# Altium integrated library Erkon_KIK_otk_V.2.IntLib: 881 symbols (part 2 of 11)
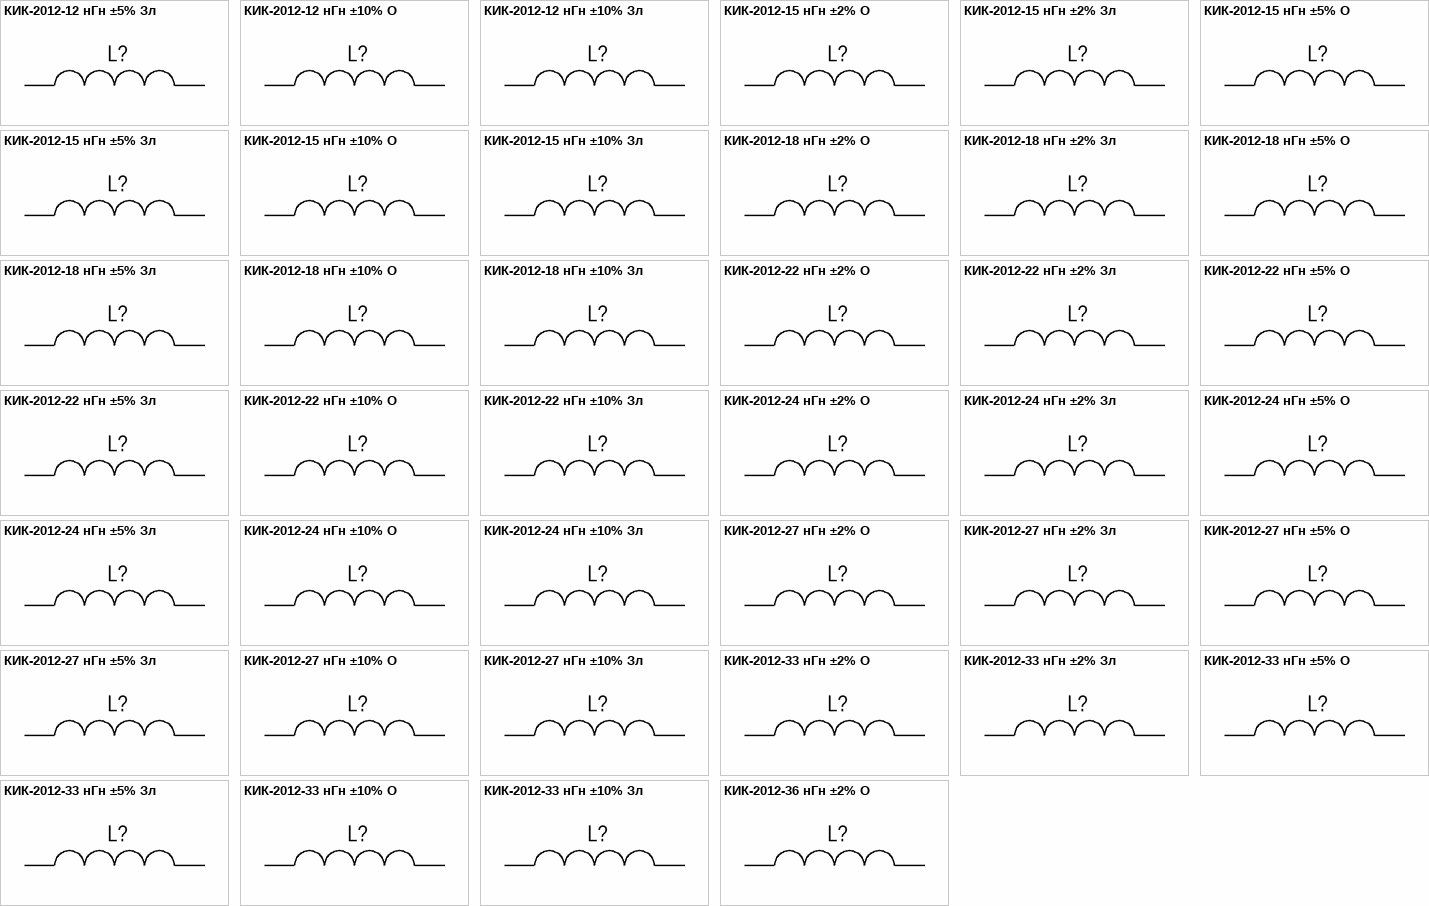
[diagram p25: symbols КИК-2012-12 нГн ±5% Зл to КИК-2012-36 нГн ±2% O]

## КИК-2012-36 нГн ±2% O
designator L?, comment 36 нГн ±2%  (value not drawn)
Катушка индуктивности с керамическим сердечником и  финишным покрытием контактных площадок оловом; Номиналиная индуктивность: 36 нГн; Добротность, не менее: 50; Резонансная частота, не менее: 1.90 ГГц; Сопротивление обмотки постоянноми току, не более: 0.27 Ом; Допустимый ток обмотки: 500 мА; Диапазон рабочих температур: от -60 до +125 ℃; Упаковка: Катушка и лента; Типоразмер: 2012 (0805); Технология монтажа: SMT; Изготовитель: АО "НПО "ЭРКОН"
footprint КИК-2012-O (Катушка индуктивности с керамическим сердечником типоразмер 2012(0805))
pins: 1, 2

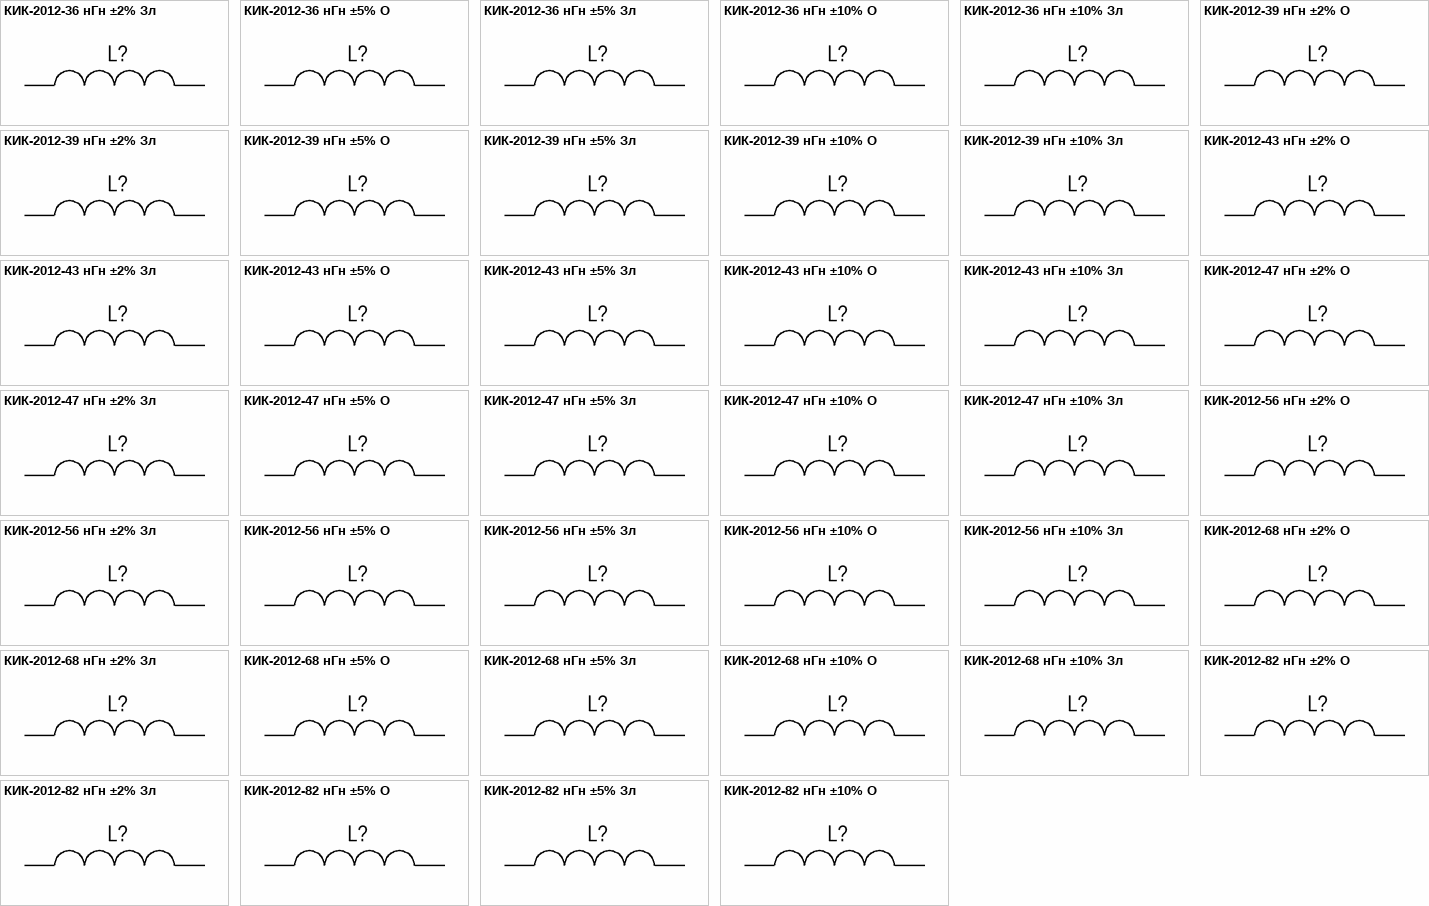
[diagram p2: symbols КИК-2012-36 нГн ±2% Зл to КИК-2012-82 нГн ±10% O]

## КИК-2012-36 нГн ±2% Зл
designator L?, comment 36 нГн ±2%  (value not drawn)
Катушка индуктивности с керамическим сердечником и золотым покрытием контактных площадок; Номиналиная индуктивность: 36 нГн; Добротность, не менее: 50; Резонансная частота, не менее: 1.90 ГГц; Сопротивление обмотки постоянноми току, не более: 0.27 Ом; Допустимый ток обмотки: 500 мА; Диапазон рабочих температур: от -60 до +125 ℃; Упаковка: Катушка и лента; Типоразмер: 2012 (0805); Технология монтажа: SMT; Изготовитель: АО "НПО "ЭРКОН"
footprint КИК-2012-Зл (Катушка индуктивности с керамическим сердечникомтипоразмер 2012(0805))
pins: 1, 2

## КИК-2012-36 нГн ±5% O
designator L?, comment 36 нГн ±5%  (value not drawn)
Катушка индуктивности с керамическим сердечником и  финишным покрытием контактных площадок оловом; Номиналиная индуктивность: 36 нГн; Добротность, не менее: 50; Резонансная частота, не менее: 1.90 ГГц; Сопротивление обмотки постоянноми току, не более: 0.27 Ом; Допустимый ток обмотки: 500 мА; Диапазон рабочих температур: от -60 до +125 ℃; Упаковка: Катушка и лента; Типоразмер: 2012 (0805); Технология монтажа: SMT; Изготовитель: АО "НПО "ЭРКОН"
footprint КИК-2012-O (Катушка индуктивности с керамическим сердечником типоразмер 2012(0805))
pins: 1, 2

## КИК-2012-36 нГн ±5% Зл
designator L?, comment 36 нГн ±5%  (value not drawn)
Катушка индуктивности с керамическим сердечником и золотым покрытием контактных площадок; Номиналиная индуктивность: 36 нГн; Добротность, не менее: 50; Резонансная частота, не менее: 1.90 ГГц; Сопротивление обмотки постоянноми току, не более: 0.27 Ом; Допустимый ток обмотки: 500 мА; Диапазон рабочих температур: от -60 до +125 ℃; Упаковка: Катушка и лента; Типоразмер: 2012 (0805); Технология монтажа: SMT; Изготовитель: АО "НПО "ЭРКОН"
footprint КИК-2012-Зл (Катушка индуктивности с керамическим сердечникомтипоразмер 2012(0805))
pins: 1, 2

## КИК-2012-36 нГн ±10% O
designator L?, comment 36 нГн ±10%  (value not drawn)
Катушка индуктивности с керамическим сердечником и  финишным покрытием контактных площадок оловом; Номиналиная индуктивность: 36 нГн; Добротность, не менее: 50; Резонансная частота, не менее: 1.90 ГГц; Сопротивление обмотки постоянноми току, не более: 0.27 Ом; Допустимый ток обмотки: 500 мА; Диапазон рабочих температур: от -60 до +125 ℃; Упаковка: Катушка и лента; Типоразмер: 2012 (0805); Технология монтажа: SMT; Изготовитель: АО "НПО "ЭРКОН"
footprint КИК-2012-O (Катушка индуктивности с керамическим сердечником типоразмер 2012(0805))
pins: 1, 2

## КИК-2012-36 нГн ±10% Зл
designator L?, comment 36 нГн ±10%  (value not drawn)
Катушка индуктивности с керамическим сердечником и золотым покрытием контактных площадок; Номиналиная индуктивность: 36 нГн; Добротность, не менее: 50; Резонансная частота, не менее: 1.90 ГГц; Сопротивление обмотки постоянноми току, не более: 0.27 Ом; Допустимый ток обмотки: 500 мА; Диапазон рабочих температур: от -60 до +125 ℃; Упаковка: Катушка и лента; Типоразмер: 2012 (0805); Технология монтажа: SMT; Изготовитель: АО "НПО "ЭРКОН"
footprint КИК-2012-Зл (Катушка индуктивности с керамическим сердечникомтипоразмер 2012(0805))
pins: 1, 2

## КИК-2012-39 нГн ±2% O
designator L?, comment 39 нГн ±2%  (value not drawn)
Катушка индуктивности с керамическим сердечником и  финишным покрытием контактных площадок оловом; Номиналиная индуктивность: 39 нГн; Добротность, не менее: 60; Резонансная частота, не менее: 2.0 ГГц; Сопротивление обмотки постоянноми току, не более: 0.29 Ом; Допустимый ток обмотки: 500 мА; Диапазон рабочих температур: от -60 до +125 ℃; Упаковка: Катушка и лента; Типоразмер: 2012 (0805); Технология монтажа: SMT; Изготовитель: АО "НПО "ЭРКОН"
footprint КИК-2012-O (Катушка индуктивности с керамическим сердечником типоразмер 2012(0805))
pins: 1, 2

## КИК-2012-39 нГн ±2% Зл
designator L?, comment 39 нГн ±2%  (value not drawn)
Катушка индуктивности с керамическим сердечником и золотым покрытием контактных площадок; Номиналиная индуктивность: 39 нГн; Добротность, не менее: 60; Резонансная частота, не менее: 2.0 ГГц; Сопротивление обмотки постоянноми току, не более: 0.29 Ом; Допустимый ток обмотки: 500 мА; Диапазон рабочих температур: от -60 до +125 ℃; Упаковка: Катушка и лента; Типоразмер: 2012 (0805); Технология монтажа: SMT; Изготовитель: АО "НПО "ЭРКОН"
footprint КИК-2012-Зл (Катушка индуктивности с керамическим сердечникомтипоразмер 2012(0805))
pins: 1, 2

## КИК-2012-39 нГн ±5% O
designator L?, comment 39 нГн ±5%  (value not drawn)
Катушка индуктивности с керамическим сердечником и  финишным покрытием контактных площадок оловом; Номиналиная индуктивность: 39 нГн; Добротность, не менее: 60; Резонансная частота, не менее: 2.0 ГГц; Сопротивление обмотки постоянноми току, не более: 0.29 Ом; Допустимый ток обмотки: 500 мА; Диапазон рабочих температур: от -60 до +125 ℃; Упаковка: Катушка и лента; Типоразмер: 2012 (0805); Технология монтажа: SMT; Изготовитель: АО "НПО "ЭРКОН"
footprint КИК-2012-O (Катушка индуктивности с керамическим сердечником типоразмер 2012(0805))
pins: 1, 2

## КИК-2012-39 нГн ±5% Зл
designator L?, comment 39 нГн ±5%  (value not drawn)
Катушка индуктивности с керамическим сердечником и золотым покрытием контактных площадок; Номиналиная индуктивность: 39 нГн; Добротность, не менее: 60; Резонансная частота, не менее: 2.0 ГГц; Сопротивление обмотки постоянноми току, не более: 0.29 Ом; Допустимый ток обмотки: 500 мА; Диапазон рабочих температур: от -60 до +125 ℃; Упаковка: Катушка и лента; Типоразмер: 2012 (0805); Технология монтажа: SMT; Изготовитель: АО "НПО "ЭРКОН"
footprint КИК-2012-Зл (Катушка индуктивности с керамическим сердечникомтипоразмер 2012(0805))
pins: 1, 2

## КИК-2012-39 нГн ±10% O
designator L?, comment 39 нГн ±10%  (value not drawn)
Катушка индуктивности с керамическим сердечником и  финишным покрытием контактных площадок оловом; Номиналиная индуктивность: 39 нГн; Добротность, не менее: 60; Резонансная частота, не менее: 2.0 ГГц; Сопротивление обмотки постоянноми току, не более: 0.29 Ом; Допустимый ток обмотки: 500 мА; Диапазон рабочих температур: от -60 до +125 ℃; Упаковка: Катушка и лента; Типоразмер: 2012 (0805); Технология монтажа: SMT; Изготовитель: АО "НПО "ЭРКОН"
footprint КИК-2012-O (Катушка индуктивности с керамическим сердечником типоразмер 2012(0805))
pins: 1, 2

## КИК-2012-39 нГн ±10% Зл
designator L?, comment 39 нГн ±10%  (value not drawn)
Катушка индуктивности с керамическим сердечником и золотым покрытием контактных площадок; Номиналиная индуктивность: 39 нГн; Добротность, не менее: 60; Резонансная частота, не менее: 2.0 ГГц; Сопротивление обмотки постоянноми току, не более: 0.29 Ом; Допустимый ток обмотки: 500 мА; Диапазон рабочих температур: от -60 до +125 ℃; Упаковка: Катушка и лента; Типоразмер: 2012 (0805); Технология монтажа: SMT; Изготовитель: АО "НПО "ЭРКОН"
footprint КИК-2012-Зл (Катушка индуктивности с керамическим сердечникомтипоразмер 2012(0805))
pins: 1, 2

## КИК-2012-43 нГн ±2% O
designator L?, comment 43 нГн ±2%  (value not drawn)
Катушка индуктивности с керамическим сердечником и  финишным покрытием контактных площадок оловом; Номиналиная индуктивность: 43 нГн; Добротность, не менее: 60; Резонансная частота, не менее: 1.8 ГГц; Сопротивление обмотки постоянноми току, не более: 0.34 Ом; Допустимый ток обмотки: 500 мА; Диапазон рабочих температур: от -60 до +125 ℃; Упаковка: Катушка и лента; Типоразмер: 2012 (0805); Технология монтажа: SMT; Изготовитель: АО "НПО "ЭРКОН"
footprint КИК-2012-O (Катушка индуктивности с керамическим сердечником типоразмер 2012(0805))
pins: 1, 2

## КИК-2012-43 нГн ±2% Зл
designator L?, comment 43 нГн ±2%  (value not drawn)
Катушка индуктивности с керамическим сердечником и золотым покрытием контактных площадок; Номиналиная индуктивность: 43 нГн; Добротность, не менее: 60; Резонансная частота, не менее: 1.8 ГГц; Сопротивление обмотки постоянноми току, не более: 0.34 Ом; Допустимый ток обмотки: 500 мА; Диапазон рабочих температур: от -60 до +125 ℃; Упаковка: Катушка и лента; Типоразмер: 2012 (0805); Технология монтажа: SMT; Изготовитель: АО "НПО "ЭРКОН"
footprint КИК-2012-Зл (Катушка индуктивности с керамическим сердечникомтипоразмер 2012(0805))
pins: 1, 2

## КИК-2012-43 нГн ±5% O
designator L?, comment 43 нГн ±5%  (value not drawn)
Катушка индуктивности с керамическим сердечником и  финишным покрытием контактных площадок оловом; Номиналиная индуктивность: 43 нГн; Добротность, не менее: 60; Резонансная частота, не менее: 1.8 ГГц; Сопротивление обмотки постоянноми току, не более: 0.34 Ом; Допустимый ток обмотки: 500 мА; Диапазон рабочих температур: от -60 до +125 ℃; Упаковка: Катушка и лента; Типоразмер: 2012 (0805); Технология монтажа: SMT; Изготовитель: АО "НПО "ЭРКОН"
footprint КИК-2012-O (Катушка индуктивности с керамическим сердечником типоразмер 2012(0805))
pins: 1, 2

## КИК-2012-43 нГн ±5% Зл
designator L?, comment 43 нГн ±5%  (value not drawn)
Катушка индуктивности с керамическим сердечником и золотым покрытием контактных площадок; Номиналиная индуктивность: 43 нГн; Добротность, не менее: 60; Резонансная частота, не менее: 1.8 ГГц; Сопротивление обмотки постоянноми току, не более: 0.34 Ом; Допустимый ток обмотки: 500 мА; Диапазон рабочих температур: от -60 до +125 ℃; Упаковка: Катушка и лента; Типоразмер: 2012 (0805); Технология монтажа: SMT; Изготовитель: АО "НПО "ЭРКОН"
footprint КИК-2012-Зл (Катушка индуктивности с керамическим сердечникомтипоразмер 2012(0805))
pins: 1, 2

## КИК-2012-43 нГн ±10% O
designator L?, comment 43 нГн ±10%  (value not drawn)
Катушка индуктивности с керамическим сердечником и  финишным покрытием контактных площадок оловом; Номиналиная индуктивность: 43 нГн; Добротность, не менее: 60; Резонансная частота, не менее: 1.8 ГГц; Сопротивление обмотки постоянноми току, не более: 0.34 Ом; Допустимый ток обмотки: 500 мА; Диапазон рабочих температур: от -60 до +125 ℃; Упаковка: Катушка и лента; Типоразмер: 2012 (0805); Технология монтажа: SMT; Изготовитель: АО "НПО "ЭРКОН"
footprint КИК-2012-O (Катушка индуктивности с керамическим сердечником типоразмер 2012(0805))
pins: 1, 2

## КИК-2012-43 нГн ±10% Зл
designator L?, comment 43 нГн ±10%  (value not drawn)
Катушка индуктивности с керамическим сердечником и золотым покрытием контактных площадок; Номиналиная индуктивность: 43 нГн; Добротность, не менее: 60; Резонансная частота, не менее: 1.8 ГГц; Сопротивление обмотки постоянноми току, не более: 0.34 Ом; Допустимый ток обмотки: 500 мА; Диапазон рабочих температур: от -60 до +125 ℃; Упаковка: Катушка и лента; Типоразмер: 2012 (0805); Технология монтажа: SMT; Изготовитель: АО "НПО "ЭРКОН"
footprint КИК-2012-Зл (Катушка индуктивности с керамическим сердечникомтипоразмер 2012(0805))
pins: 1, 2

## КИК-2012-47 нГн ±2% O
designator L?, comment 47 нГн ±2%  (value not drawn)
Катушка индуктивности с керамическим сердечником и  финишным покрытием контактных площадок оловом; Номиналиная индуктивность: 47 нГн; Допускаемое отклонение индуктивности: ±5%; Добротность, не менее: 60; Резонансная частота, не менее: 1.7 ГГц; Сопротивление обмотки постоянноми току, не более: 0.31 Ом; Допустимый ток обмотки: 500 мА; Диапазон рабочих температур: от -60 до +125 ℃; Упаковка: Катушка и лента; Типоразмер: 2012 (0805); Технология монтажа: SMT; Изготовитель: АО "НПО "ЭРКОН"
footprint КИК-2012-O (Катушка индуктивности с керамическим сердечником типоразмер 2012(0805))
pins: 1, 2

## КИК-2012-47 нГн ±2% Зл
designator L?, comment 47 нГн ±2%  (value not drawn)
Катушка индуктивности с керамическим сердечником и золотым покрытием контактных площадок; Номиналиная индуктивность: 47 нГн; Добротность, не менее: 60; Резонансная частота, не менее: 1.7 ГГц; Сопротивление обмотки постоянноми току, не более: 0.31 Ом; Допустимый ток обмотки: 500 мА; Диапазон рабочих температур: от -60 до +125 ℃; Упаковка: Катушка и лента; Типоразмер: 2012 (0805); Технология монтажа: SMT; Изготовитель: АО "НПО "ЭРКОН"
footprint КИК-2012-Зл (Катушка индуктивности с керамическим сердечникомтипоразмер 2012(0805))
pins: 1, 2

## КИК-2012-47 нГн ±5% O
designator L?, comment 47 нГн ±5%  (value not drawn)
Катушка индуктивности с керамическим сердечником и  финишным покрытием контактных площадок оловом; Номиналиная индуктивность: 47 нГн; Добротность, не менее: 60; Резонансная частота, не менее: 1.7 ГГц; Сопротивление обмотки постоянноми току, не более: 0.31 Ом; Допустимый ток обмотки: 500 мА; Диапазон рабочих температур: от -60 до +125 ℃; Упаковка: Катушка и лента; Типоразмер: 2012 (0805); Технология монтажа: SMT; Изготовитель: АО "НПО "ЭРКОН"
footprint КИК-2012-O (Катушка индуктивности с керамическим сердечником типоразмер 2012(0805))
pins: 1, 2

## КИК-2012-47 нГн ±5% Зл
designator L?, comment 47 нГн ±5%  (value not drawn)
Катушка индуктивности с керамическим сердечником и золотым покрытием контактных площадок; Номиналиная индуктивность: 47 нГн; Добротность, не менее: 60; Резонансная частота, не менее: 1.7 ГГц; Сопротивление обмотки постоянноми току, не более: 0.31 Ом; Допустимый ток обмотки: 500 мА; Диапазон рабочих температур: от -60 до +125 ℃; Упаковка: Катушка и лента; Типоразмер: 2012 (0805); Технология монтажа: SMT; Изготовитель: АО "НПО "ЭРКОН"
footprint КИК-2012-Зл (Катушка индуктивности с керамическим сердечникомтипоразмер 2012(0805))
pins: 1, 2

## КИК-2012-47 нГн ±10% O
designator L?, comment 47 нГн ±10%  (value not drawn)
Катушка индуктивности с керамическим сердечником и  финишным покрытием контактных площадок оловом; Номиналиная индуктивность: 47 нГн; Добротность, не менее: 60; Резонансная частота, не менее: 1.7 ГГц; Сопротивление обмотки постоянноми току, не более: 0.31 Ом; Допустимый ток обмотки: 500 мА; Диапазон рабочих температур: от -60 до +125 ℃; Упаковка: Катушка и лента; Типоразмер: 2012 (0805); Технология монтажа: SMT; Изготовитель: АО "НПО "ЭРКОН"
footprint КИК-2012-O (Катушка индуктивности с керамическим сердечником типоразмер 2012(0805))
pins: 1, 2

## КИК-2012-47 нГн ±10% Зл
designator L?, comment 47 нГн ±10%  (value not drawn)
Катушка индуктивности с керамическим сердечником и золотым покрытием контактных площадок; Номиналиная индуктивность: 47 нГн; Добротность, не менее: 60; Резонансная частота, не менее: 1.7 ГГц; Сопротивление обмотки постоянноми току, не более: 0.31 Ом; Допустимый ток обмотки: 500 мА; Диапазон рабочих температур: от -60 до +125 ℃; Упаковка: Катушка и лента; Типоразмер: 2012 (0805); Технология монтажа: SMT; Изготовитель: АО "НПО "ЭРКОН"
footprint КИК-2012-Зл (Катушка индуктивности с керамическим сердечникомтипоразмер 2012(0805))
pins: 1, 2

## КИК-2012-56 нГн ±2% O
designator L?, comment 47 нГн ±2%  (value not drawn)
Катушка индуктивности с керамическим сердечником и  финишным покрытием контактных площадок оловом; Номиналиная индуктивность: 56 нГн; Добротность, не менее: 60; Резонансная частота, не менее: 1.6 ГГц; Сопротивление обмотки постоянноми току, не более: 0.34 Ом; Допустимый ток обмотки: 500 мА; Диапазон рабочих температур: от -60 до +125 ℃; Упаковка: Катушка и лента; Типоразмер: 2012 (0805); Технология монтажа: SMT; Изготовитель: АО "НПО "ЭРКОН"
footprint КИК-2012-O (Катушка индуктивности с керамическим сердечником типоразмер 2012(0805))
pins: 1, 2

## КИК-2012-56 нГн ±2% Зл
designator L?, comment 56 нГн ±2%  (value not drawn)
Катушка индуктивности с керамическим сердечником и золотым покрытием контактных площадок; Номиналиная индуктивность: 56 нГн; Добротность, не менее: 60; Резонансная частота, не менее: 1.6 ГГц; Сопротивление обмотки постоянноми току, не более: 0.34 Ом; Допустимый ток обмотки: 500 мА; Диапазон рабочих температур: от -60 до +125 ℃; Упаковка: Катушка и лента; Типоразмер: 2012 (0805); Технология монтажа: SMT; Изготовитель: АО "НПО "ЭРКОН"
footprint КИК-2012-Зл (Катушка индуктивности с керамическим сердечникомтипоразмер 2012(0805))
pins: 1, 2

## КИК-2012-56 нГн ±5% O
designator L?, comment 47 нГн ±5%  (value not drawn)
Катушка индуктивности с керамическим сердечником и  финишным покрытием контактных площадок оловом; Номиналиная индуктивность: 56 нГн; Добротность, не менее: 60; Резонансная частота, не менее: 1.6 ГГц; Сопротивление обмотки постоянноми току, не более: 0.34 Ом; Допустимый ток обмотки: 500 мА; Диапазон рабочих температур: от -60 до +125 ℃; Упаковка: Катушка и лента; Типоразмер: 2012 (0805); Технология монтажа: SMT; Изготовитель: АО "НПО "ЭРКОН"
footprint КИК-2012-O (Катушка индуктивности с керамическим сердечником типоразмер 2012(0805))
pins: 1, 2

## КИК-2012-56 нГн ±5% Зл
designator L?, comment 56 нГн ±5%  (value not drawn)
Катушка индуктивности с керамическим сердечником и золотым покрытием контактных площадок; Номиналиная индуктивность: 56 нГн; Добротность, не менее: 60; Резонансная частота, не менее: 1.6 ГГц; Сопротивление обмотки постоянноми току, не более: 0.34 Ом; Допустимый ток обмотки: 500 мА; Диапазон рабочих температур: от -60 до +125 ℃; Упаковка: Катушка и лента; Типоразмер: 2012 (0805); Технология монтажа: SMT; Изготовитель: АО "НПО "ЭРКОН"
footprint КИК-2012-Зл (Катушка индуктивности с керамическим сердечникомтипоразмер 2012(0805))
pins: 1, 2

## КИК-2012-56 нГн ±10% O
designator L?, comment 56 нГн ±10%  (value not drawn)
Катушка индуктивности с керамическим сердечником и  финишным покрытием контактных площадок оловом; Номиналиная индуктивность: 56 нГн; Добротность, не менее: 60; Резонансная частота, не менее: 1.6 ГГц; Сопротивление обмотки постоянноми току, не более: 0.34 Ом; Допустимый ток обмотки: 500 мА; Диапазон рабочих температур: от -60 до +125 ℃; Упаковка: Катушка и лента; Типоразмер: 2012 (0805); Технология монтажа: SMT; Изготовитель: АО "НПО "ЭРКОН"
footprint КИК-2012-O (Катушка индуктивности с керамическим сердечником типоразмер 2012(0805))
pins: 1, 2

## КИК-2012-56 нГн ±10% Зл
designator L?, comment 56 нГн ±10%  (value not drawn)
Катушка индуктивности с керамическим сердечником и золотым покрытием контактных площадок; Номиналиная индуктивность: 56 нГн; Добротность, не менее: 60; Резонансная частота, не менее: 1.6 ГГц; Сопротивление обмотки постоянноми току, не более: 0.34 Ом; Допустимый ток обмотки: 500 мА; Диапазон рабочих температур: от -60 до +125 ℃; Упаковка: Катушка и лента; Типоразмер: 2012 (0805); Технология монтажа: SMT; Изготовитель: АО "НПО "ЭРКОН"
footprint КИК-2012-Зл (Катушка индуктивности с керамическим сердечникомтипоразмер 2012(0805))
pins: 1, 2

## КИК-2012-68 нГн ±2% O
designator L?, comment 68 нГн ±2%  (value not drawn)
Катушка индуктивности с керамическим сердечником и  финишным покрытием контактных площадок оловом; Номиналиная индуктивность: 68 нГн; Добротность, не менее: 60; Резонансная частота, не менее: 1.5 ГГц; Сопротивление обмотки постоянноми току, не более: 0.38 Ом; Допустимый ток обмотки: 500 мА; Диапазон рабочих температур: от -60 до +125 ℃; Упаковка: Катушка и лента; Типоразмер: 2012 (0805); Технология монтажа: SMT; Изготовитель: АО "НПО "ЭРКОН"
footprint КИК-2012-O (Катушка индуктивности с керамическим сердечником типоразмер 2012(0805))
pins: 1, 2

## КИК-2012-68 нГн ±2% Зл
designator L?, comment 68 нГн ±2%  (value not drawn)
Катушка индуктивности с керамическим сердечником и золотым покрытием контактных площадок; Номиналиная индуктивность: 68 нГн; Добротность, не менее: 60; Резонансная частота, не менее: 1.5 ГГц; Сопротивление обмотки постоянноми току, не более: 0.38 Ом; Допустимый ток обмотки: 500 мА; Диапазон рабочих температур: от -60 до +125 ℃; Упаковка: Катушка и лента; Типоразмер: 2012 (0805); Технология монтажа: SMT; Изготовитель: АО "НПО "ЭРКОН"
footprint КИК-2012-Зл (Катушка индуктивности с керамическим сердечникомтипоразмер 2012(0805))
pins: 1, 2

## КИК-2012-68 нГн ±5% O
designator L?, comment 68 нГн ±5%  (value not drawn)
Катушка индуктивности с керамическим сердечником и  финишным покрытием контактных площадок оловом; Номиналиная индуктивность: 68 нГн; Добротность, не менее: 60; Резонансная частота, не менее: 1.5 ГГц; Сопротивление обмотки постоянноми току, не более: 0.38 Ом; Допустимый ток обмотки: 500 мА; Диапазон рабочих температур: от -60 до +125 ℃; Упаковка: Катушка и лента; Типоразмер: 2012 (0805); Технология монтажа: SMT; Изготовитель: АО "НПО "ЭРКОН"
footprint КИК-2012-O (Катушка индуктивности с керамическим сердечником типоразмер 2012(0805))
pins: 1, 2

## КИК-2012-68 нГн ±5% Зл
designator L?, comment 68 нГн ±5%  (value not drawn)
Катушка индуктивности с керамическим сердечником и золотым покрытием контактных площадок; Номиналиная индуктивность: 68 нГн; Добротность, не менее: 60; Резонансная частота, не менее: 1.5 ГГц; Сопротивление обмотки постоянноми току, не более: 0.38 Ом; Допустимый ток обмотки: 500 мА; Диапазон рабочих температур: от -60 до +125 ℃; Упаковка: Катушка и лента; Типоразмер: 2012 (0805); Технология монтажа: SMT; Изготовитель: АО "НПО "ЭРКОН"
footprint КИК-2012-Зл (Катушка индуктивности с керамическим сердечникомтипоразмер 2012(0805))
pins: 1, 2

## КИК-2012-68 нГн ±10% O
designator L?, comment 68 нГн ±10%  (value not drawn)
Катушка индуктивности с керамическим сердечником и  финишным покрытием контактных площадок оловом; Номиналиная индуктивность: 68 нГн; Добротность, не менее: 60; Резонансная частота, не менее: 1.5 ГГц; Сопротивление обмотки постоянноми току, не более: 0.38 Ом; Допустимый ток обмотки: 500 мА; Диапазон рабочих температур: от -60 до +125 ℃; Упаковка: Катушка и лента; Типоразмер: 2012 (0805); Технология монтажа: SMT; Изготовитель: АО "НПО "ЭРКОН"
footprint КИК-2012-O (Катушка индуктивности с керамическим сердечником типоразмер 2012(0805))
pins: 1, 2

## КИК-2012-68 нГн ±10% Зл
designator L?, comment 68 нГн ±10%  (value not drawn)
Катушка индуктивности с керамическим сердечником и золотым покрытием контактных площадок; Номиналиная индуктивность: 68 нГн; Добротность, не менее: 60; Резонансная частота, не менее: 1.5 ГГц; Сопротивление обмотки постоянноми току, не более: 0.38 Ом; Допустимый ток обмотки: 500 мА; Диапазон рабочих температур: от -60 до +125 ℃; Упаковка: Катушка и лента; Типоразмер: 2012 (0805); Технология монтажа: SMT; Изготовитель: АО "НПО "ЭРКОН"
footprint КИК-2012-Зл (Катушка индуктивности с керамическим сердечникомтипоразмер 2012(0805))
pins: 1, 2

## КИК-2012-82 нГн ±2% O
designator L?, comment 82 нГн ±2%  (value not drawn)
Катушка индуктивности с керамическим сердечником и  финишным покрытием контактных площадок оловом; Номиналиная индуктивность: 82 нГн; Добротность, не менее: 60; Резонансная частота, не менее: 1.33 ГГц; Сопротивление обмотки постоянноми току, не более: 0.42 Ом; Допустимый ток обмотки: 400 мА; Диапазон рабочих температур: от -60 до +125 ℃; Упаковка: Катушка и лента; Типоразмер: 2012 (0805); Технология монтажа: SMT; Изготовитель: АО "НПО "ЭРКОН"
footprint КИК-2012-O (Катушка индуктивности с керамическим сердечником типоразмер 2012(0805))
pins: 1, 2

## КИК-2012-82 нГн ±2% Зл
designator L?, comment 82 нГн ±2%  (value not drawn)
Катушка индуктивности с керамическим сердечником и золотым покрытием контактных площадок; Номиналиная индуктивность: 82 нГн; Добротность, не менее: 60; Резонансная частота, не менее: 1.33 ГГц; Сопротивление обмотки постоянноми току, не более: 0.42 Ом; Допустимый ток обмотки: 400 мА; Диапазон рабочих температур: от -60 до +125 ℃; Упаковка: Катушка и лента; Типоразмер: 2012 (0805); Технология монтажа: SMT; Изготовитель: АО "НПО "ЭРКОН"
footprint КИК-2012-Зл (Катушка индуктивности с керамическим сердечникомтипоразмер 2012(0805))
pins: 1, 2

## КИК-2012-82 нГн ±5% O
designator L?, comment 82 нГн ±5%  (value not drawn)
Катушка индуктивности с керамическим сердечником и  финишным покрытием контактных площадок оловом; Номиналиная индуктивность: 82 нГн; Добротность, не менее: 60; Резонансная частота, не менее: 1.33 ГГц; Сопротивление обмотки постоянноми току, не более: 0.42 Ом; Допустимый ток обмотки: 400 мА; Диапазон рабочих температур: от -60 до +125 ℃; Упаковка: Катушка и лента; Типоразмер: 2012 (0805); Технология монтажа: SMT; Изготовитель: АО "НПО "ЭРКОН"
footprint КИК-2012-O (Катушка индуктивности с керамическим сердечником типоразмер 2012(0805))
pins: 1, 2

## КИК-2012-82 нГн ±5% Зл
designator L?, comment 82 нГн ±5%  (value not drawn)
Катушка индуктивности с керамическим сердечником и золотым покрытием контактных площадок; Номиналиная индуктивность: 82 нГн; Добротность, не менее: 60; Резонансная частота, не менее: 1.33 ГГц; Сопротивление обмотки постоянноми току, не более: 0.42 Ом; Допустимый ток обмотки: 400 мА; Диапазон рабочих температур: от -60 до +125 ℃; Упаковка: Катушка и лента; Типоразмер: 2012 (0805); Технология монтажа: SMT; Изготовитель: АО "НПО "ЭРКОН"
footprint КИК-2012-Зл (Катушка индуктивности с керамическим сердечникомтипоразмер 2012(0805))
pins: 1, 2

## КИК-2012-82 нГн ±10% O
designator L?, comment 82 нГн ±10%  (value not drawn)
Катушка индуктивности с керамическим сердечником и  финишным покрытием контактных площадок оловом; Номиналиная индуктивность: 82 нГн; Добротность, не менее: 60; Резонансная частота, не менее: 1.33 ГГц; Сопротивление обмотки постоянноми току, не более: 0.42 Ом; Допустимый ток обмотки: 400 мА; Диапазон рабочих температур: от -60 до +125 ℃; Упаковка: Катушка и лента; Типоразмер: 2012 (0805); Технология монтажа: SMT; Изготовитель: АО "НПО "ЭРКОН"
footprint КИК-2012-O (Катушка индуктивности с керамическим сердечником типоразмер 2012(0805))
pins: 1, 2

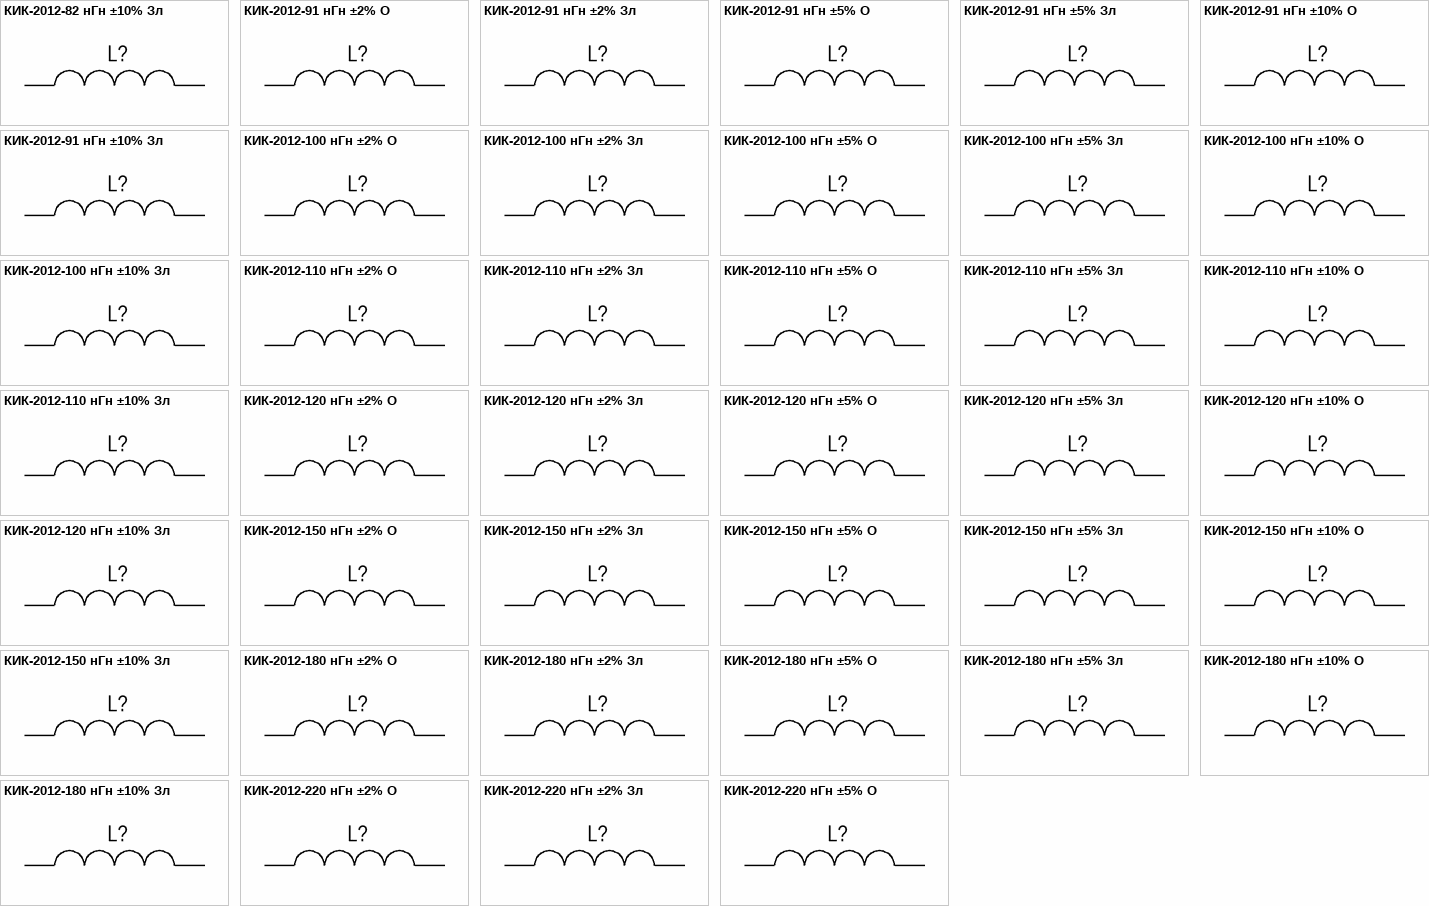
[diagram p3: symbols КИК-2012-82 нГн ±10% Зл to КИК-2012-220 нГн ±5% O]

## КИК-2012-82 нГн ±10% Зл
designator L?, comment 82 нГн ±10%  (value not drawn)
Катушка индуктивности с керамическим сердечником и золотым покрытием контактных площадок; Номиналиная индуктивность: 82 нГн; Добротность, не менее: 60; Резонансная частота, не менее: 1.33 ГГц; Сопротивление обмотки постоянноми току, не более: 0.42 Ом; Допустимый ток обмотки: 400 мА; Диапазон рабочих температур: от -60 до +125 ℃; Упаковка: Катушка и лента; Типоразмер: 2012 (0805); Технология монтажа: SMT; Изготовитель: АО "НПО "ЭРКОН"
footprint КИК-2012-Зл (Катушка индуктивности с керамическим сердечникомтипоразмер 2012(0805))
pins: 1, 2

## КИК-2012-91 нГн ±2% O
designator L?, comment 91 нГн ±2%  (value not drawn)
Катушка индуктивности с керамическим сердечником и  финишным покрытием контактных площадок оловом; Номиналиная индуктивность: 91нГн; Добротность, не менее: 60; Резонансная частота, не менее: 1.33 ГГц; Сопротивление обмотки постоянноми току, не более: 0.48 Ом; Допустимый ток обмотки: 400 мА; Диапазон рабочих температур: от -60 до +125 ℃; Упаковка: Катушка и лента; Типоразмер: 2012 (0805); Технология монтажа: SMT; Изготовитель: АО "НПО "ЭРКОН"
footprint КИК-2012-O (Катушка индуктивности с керамическим сердечником типоразмер 2012(0805))
pins: 1, 2

## КИК-2012-91 нГн ±2% Зл
designator L?, comment 91 нГн ±2%  (value not drawn)
Катушка индуктивности с керамическим сердечником и золотым покрытием контактных площадок; Номиналиная индуктивность: 91нГн; Добротность, не менее: 60; Резонансная частота, не менее: 1.33 ГГц; Сопротивление обмотки постоянноми току, не более: 0.48 Ом; Допустимый ток обмотки: 400 мА; Диапазон рабочих температур: от -60 до +125 ℃; Упаковка: Катушка и лента; Типоразмер: 2012 (0805); Технология монтажа: SMT; Изготовитель: АО "НПО "ЭРКОН"
footprint КИК-2012-Зл (Катушка индуктивности с керамическим сердечникомтипоразмер 2012(0805))
pins: 1, 2

## КИК-2012-91 нГн ±5% O
designator L?, comment 91 нГн ±5%  (value not drawn)
Катушка индуктивности с керамическим сердечником и  финишным покрытием контактных площадок оловом; Номиналиная индуктивность: 91нГн; Добротность, не менее: 60; Резонансная частота, не менее: 1.33 ГГц; Сопротивление обмотки постоянноми току, не более: 0.48 Ом; Допустимый ток обмотки: 400 мА; Диапазон рабочих температур: от -60 до +125 ℃; Упаковка: Катушка и лента; Типоразмер: 2012 (0805); Технология монтажа: SMT; Изготовитель: АО "НПО "ЭРКОН"
footprint КИК-2012-O (Катушка индуктивности с керамическим сердечником типоразмер 2012(0805))
pins: 1, 2

## КИК-2012-91 нГн ±5% Зл
designator L?, comment 91 нГн ±5%  (value not drawn)
Катушка индуктивности с керамическим сердечником и золотым покрытием контактных площадок; Номиналиная индуктивность: 91нГн; Добротность, не менее: 60; Резонансная частота, не менее: 1.33 ГГц; Сопротивление обмотки постоянноми току, не более: 0.48 Ом; Допустимый ток обмотки: 400 мА; Диапазон рабочих температур: от -60 до +125 ℃; Упаковка: Катушка и лента; Типоразмер: 2012 (0805); Технология монтажа: SMT; Изготовитель: АО "НПО "ЭРКОН"
footprint КИК-2012-Зл (Катушка индуктивности с керамическим сердечникомтипоразмер 2012(0805))
pins: 1, 2

## КИК-2012-91 нГн ±10% O
designator L?, comment 91 нГн ±10%  (value not drawn)
Катушка индуктивности с керамическим сердечником и  финишным покрытием контактных площадок оловом; Номиналиная индуктивность: 91 нГн; Добротность, не менее: 60; Резонансная частота, не менее: 1.33 ГГц; Сопротивление обмотки постоянноми току, не более: 0.48 Ом; Допустимый ток обмотки: 400 мА; Диапазон рабочих температур: от -60 до +125 ℃; Упаковка: Катушка и лента; Типоразмер: 2012 (0805); Технология монтажа: SMT; Изготовитель: АО "НПО "ЭРКОН"
footprint КИК-2012-O (Катушка индуктивности с керамическим сердечником типоразмер 2012(0805))
pins: 1, 2

## КИК-2012-91 нГн ±10% Зл
designator L?, comment 91 нГн ±10%  (value not drawn)
Катушка индуктивности с керамическим сердечником и золотым покрытием контактных площадок; Номиналиная индуктивность: 91нГн; Добротность, не менее: 60; Резонансная частота, не менее: 1.33 ГГц; Сопротивление обмотки постоянноми току, не более: 0.48 Ом; Допустимый ток обмотки: 400 мА; Диапазон рабочих температур: от -60 до +125 ℃; Упаковка: Катушка и лента; Типоразмер: 2012 (0805); Технология монтажа: SMT; Изготовитель: АО "НПО "ЭРКОН"
footprint КИК-2012-Зл (Катушка индуктивности с керамическим сердечникомтипоразмер 2012(0805))
pins: 1, 2

## КИК-2012-100 нГн ±2% O
designator L?, comment 100 нГн ±2%  (value not drawn)
Катушка индуктивности с керамическим сердечником и  финишным покрытием контактных площадок оловом; Номиналиная индуктивность: 100 нГн; Добротность, не менее: 60; Резонансная частота, не менее: 1.25 ГГц; Сопротивление обмотки постоянноми току, не более: 0.46 Ом; Допустимый ток обмотки: 400 мА; Диапазон рабочих температур: от -60 до +125 ℃; Упаковка: Катушка и лента; Типоразмер: 2012 (0805); Технология монтажа: SMT; Изготовитель: АО "НПО "ЭРКОН"
footprint КИК-2012-O (Катушка индуктивности с керамическим сердечником типоразмер 2012(0805))
pins: 1, 2

## КИК-2012-100 нГн ±2% Зл
designator L?, comment 100 нГн ±2%  (value not drawn)
Катушка индуктивности с керамическим сердечником и золотым покрытием контактных площадок; Номиналиная индуктивность: 100 нГн; Добротность, не менее: 60; Резонансная частота, не менее: 1.25 ГГц; Сопротивление обмотки постоянноми току, не более: 0.46 Ом; Допустимый ток обмотки: 400 мА; Диапазон рабочих температур: от -60 до +125 ℃; Упаковка: Катушка и лента; Типоразмер: 2012 (0805); Технология монтажа: SMT; Изготовитель: АО "НПО "ЭРКОН"
footprint КИК-2012-Зл (Катушка индуктивности с керамическим сердечникомтипоразмер 2012(0805))
pins: 1, 2

## КИК-2012-100 нГн ±5% O
designator L?, comment 100 нГн ±5%  (value not drawn)
Катушка индуктивности с керамическим сердечником и  финишным покрытием контактных площадок оловом; Номиналиная индуктивность: 100 нГн; Добротность, не менее: 60; Резонансная частота, не менее: 1.25 ГГц; Сопротивление обмотки постоянноми току, не более: 0.46 Ом; Допустимый ток обмотки: 400 мА; Диапазон рабочих температур: от -60 до +125 ℃; Упаковка: Катушка и лента; Типоразмер: 2012 (0805); Технология монтажа: SMT; Изготовитель: АО "НПО "ЭРКОН"
footprint КИК-2012-O (Катушка индуктивности с керамическим сердечником типоразмер 2012(0805))
pins: 1, 2

## КИК-2012-100 нГн ±5% Зл
designator L?, comment 100 нГн ±5%  (value not drawn)
Катушка индуктивности с керамическим сердечником и золотым покрытием контактных площадок; Номиналиная индуктивность: 100 нГн; Добротность, не менее: 60; Резонансная частота, не менее: 1.25 ГГц; Сопротивление обмотки постоянноми току, не более: 0.46 Ом; Допустимый ток обмотки: 400 мА; Диапазон рабочих температур: от -60 до +125 ℃; Упаковка: Катушка и лента; Типоразмер: 2012 (0805); Технология монтажа: SMT; Изготовитель: АО "НПО "ЭРКОН"
footprint КИК-2012-Зл (Катушка индуктивности с керамическим сердечникомтипоразмер 2012(0805))
pins: 1, 2

## КИК-2012-100 нГн ±10% O
designator L?, comment 100 нГн ±10%  (value not drawn)
Катушка индуктивности с керамическим сердечником и  финишным покрытием контактных площадок оловом; Номиналиная индуктивность: 100 нГн; Добротность, не менее: 60; Резонансная частота, не менее: 1.25 ГГц; Сопротивление обмотки постоянноми току, не более: 0.46 Ом; Допустимый ток обмотки: 400 мА; Диапазон рабочих температур: от -60 до +125 ℃; Упаковка: Катушка и лента; Типоразмер: 2012 (0805); Технология монтажа: SMT; Изготовитель: АО "НПО "ЭРКОН"
footprint КИК-2012-O (Катушка индуктивности с керамическим сердечником типоразмер 2012(0805))
pins: 1, 2

## КИК-2012-100 нГн ±10% Зл
designator L?, comment 100 нГн ±10%  (value not drawn)
Катушка индуктивности с керамическим сердечником и золотым покрытием контактных площадок; Номиналиная индуктивность: 100 нГн; Добротность, не менее: 60; Резонансная частота, не менее: 1.25 ГГц; Сопротивление обмотки постоянноми току, не более: 0.46 Ом; Допустимый ток обмотки: 400 мА; Диапазон рабочих температур: от -60 до +125 ℃; Упаковка: Катушка и лента; Типоразмер: 2012 (0805); Технология монтажа: SMT; Изготовитель: АО "НПО "ЭРКОН"
footprint КИК-2012-Зл (Катушка индуктивности с керамическим сердечникомтипоразмер 2012(0805))
pins: 1, 2

## КИК-2012-110 нГн ±2% O
designator L?, comment 110 нГн ±2%  (value not drawn)
Катушка индуктивности с керамическим сердечником и  финишным покрытием контактных площадок оловом; Номиналиная индуктивность: 110 нГн; Добротность, не менее: 50; Резонансная частота, не менее: 1.10ГГц; Сопротивление обмотки постоянноми току, не более: 0.48 Ом; Допустимый ток обмотки: 400 мА; Диапазон рабочих температур: от -60 до +125 ℃; Упаковка: Катушка и лента; Типоразмер: 2012 (0805); Технология монтажа: SMT; Изготовитель: АО "НПО "ЭРКОН"
footprint КИК-2012-O (Катушка индуктивности с керамическим сердечником типоразмер 2012(0805))
pins: 1, 2

## КИК-2012-110 нГн ±2% Зл
designator L?, comment 110 нГн ±2%  (value not drawn)
Катушка индуктивности с керамическим сердечником и золотым покрытием контактных площадок; Номиналиная индуктивность: 110 нГн; Добротность, не менее: 50; Резонансная частота, не менее: 1.10ГГц; Сопротивление обмотки постоянноми току, не более: 0.48 Ом; Допустимый ток обмотки: 400 мА; Диапазон рабочих температур: от -60 до +125 ℃; Упаковка: Катушка и лента; Типоразмер: 2012 (0805); Технология монтажа: SMT; Изготовитель: АО "НПО "ЭРКОН"
footprint КИК-2012-Зл (Катушка индуктивности с керамическим сердечникомтипоразмер 2012(0805))
pins: 1, 2

## КИК-2012-110 нГн ±5% O
designator L?, comment 110 нГн ±5%  (value not drawn)
Катушка индуктивности с керамическим сердечником и  финишным покрытием контактных площадок оловом; Номиналиная индуктивность: 110 нГн; Добротность, не менее: 50; Резонансная частота, не менее: 1.10ГГц; Сопротивление обмотки постоянноми току, не более: 0.48 Ом; Допустимый ток обмотки: 400 мА; Диапазон рабочих температур: от -60 до +125 ℃; Упаковка: Катушка и лента; Типоразмер: 2012 (0805); Технология монтажа: SMT; Изготовитель: АО "НПО "ЭРКОН"
footprint КИК-2012-O (Катушка индуктивности с керамическим сердечником типоразмер 2012(0805))
pins: 1, 2

## КИК-2012-110 нГн ±5% Зл
designator L?, comment 110 нГн ±5%  (value not drawn)
Катушка индуктивности с керамическим сердечником и золотым покрытием контактных площадок; Номиналиная индуктивность: 110 нГн; Добротность, не менее: 50; Резонансная частота, не менее: 1.10ГГц; Сопротивление обмотки постоянноми току, не более: 0.48 Ом; Допустимый ток обмотки: 400 мА; Диапазон рабочих температур: от -60 до +125 ℃; Упаковка: Катушка и лента; Типоразмер: 2012 (0805); Технология монтажа: SMT; Изготовитель: АО "НПО "ЭРКОН"
footprint КИК-2012-Зл (Катушка индуктивности с керамическим сердечникомтипоразмер 2012(0805))
pins: 1, 2

## КИК-2012-110 нГн ±10% O
designator L?, comment 110 нГн ±10%  (value not drawn)
Катушка индуктивности с керамическим сердечником и  финишным покрытием контактных площадок оловом; Номиналиная индуктивность: 110 нГн; Добротность, не менее: 50; Резонансная частота, не менее: 1.10ГГц; Сопротивление обмотки постоянноми току, не более: 0.48 Ом; Допустимый ток обмотки: 400 мА; Диапазон рабочих температур: от -60 до +125 ℃; Упаковка: Катушка и лента; Типоразмер: 2012 (0805); Технология монтажа: SMT; Изготовитель: АО "НПО "ЭРКОН"
footprint КИК-2012-O (Катушка индуктивности с керамическим сердечником типоразмер 2012(0805))
pins: 1, 2

## КИК-2012-110 нГн ±10% Зл
designator L?, comment 110 нГн ±10%  (value not drawn)
Катушка индуктивности с керамическим сердечником и золотым покрытием контактных площадок; Номиналиная индуктивность: 110 нГн; Добротность, не менее: 50; Резонансная частота, не менее: 1.10ГГц; Сопротивление обмотки постоянноми току, не более: 0.48 Ом; Допустимый ток обмотки: 400 мА; Диапазон рабочих температур: от -60 до +125 ℃; Упаковка: Катушка и лента; Типоразмер: 2012 (0805); Технология монтажа: SMT; Изготовитель: АО "НПО "ЭРКОН"
footprint КИК-2012-Зл (Катушка индуктивности с керамическим сердечникомтипоразмер 2012(0805))
pins: 1, 2

## КИК-2012-120 нГн ±2% O
designator L?, comment 120 нГн ±2%  (value not drawn)
Катушка индуктивности с керамическим сердечником и  финишным покрытием контактных площадок оловом; Номиналиная индуктивность: 120 нГн; Добротность, не менее: 50; Резонансная частота, не менее: 1.10 ГГц; Сопротивление обмотки постоянноми току, не более: 0.51 Ом; Допустимый ток обмотки: 400 мА; Диапазон рабочих температур: от -60 до +125 ℃; Упаковка: Катушка и лента; Типоразмер: 2012 (0805); Технология монтажа: SMT; Изготовитель: АО "НПО "ЭРКОН"
footprint КИК-2012-O (Катушка индуктивности с керамическим сердечником типоразмер 2012(0805))
pins: 1, 2

## КИК-2012-120 нГн ±2% Зл
designator L?, comment 120 нГн ±2%  (value not drawn)
Катушка индуктивности с керамическим сердечником и золотым покрытием контактных площадок; Номиналиная индуктивность: 120 нГн; Добротность, не менее: 50; Резонансная частота, не менее: 1.10 ГГц; Сопротивление обмотки постоянноми току, не более: 0.51 Ом; Допустимый ток обмотки: 400 мА; Диапазон рабочих температур: от -60 до +125 ℃; Упаковка: Катушка и лента; Типоразмер: 2012 (0805); Технология монтажа: SMT; Изготовитель: АО "НПО "ЭРКОН"
footprint КИК-2012-Зл (Катушка индуктивности с керамическим сердечникомтипоразмер 2012(0805))
pins: 1, 2

## КИК-2012-120 нГн ±5% O
designator L?, comment 120 нГн ±5%  (value not drawn)
Катушка индуктивности с керамическим сердечником и  финишным покрытием контактных площадок оловом; Номиналиная индуктивность: 120 нГн; Добротность, не менее: 50; Резонансная частота, не менее: 1.10 ГГц; Сопротивление обмотки постоянноми току, не более: 0.51 Ом; Допустимый ток обмотки: 400 мА; Диапазон рабочих температур: от -60 до +125 ℃; Упаковка: Катушка и лента; Типоразмер: 2012 (0805); Технология монтажа: SMT; Изготовитель: АО "НПО "ЭРКОН"
footprint КИК-2012-O (Катушка индуктивности с керамическим сердечником типоразмер 2012(0805))
pins: 1, 2

## КИК-2012-120 нГн ±5% Зл
designator L?, comment 120 нГн ±5%  (value not drawn)
Катушка индуктивности с керамическим сердечником и золотым покрытием контактных площадок; Номиналиная индуктивность: 120 нГн; Добротность, не менее: 50; Резонансная частота, не менее: 1.10 ГГц; Сопротивление обмотки постоянноми току, не более: 0.51 Ом; Допустимый ток обмотки: 400 мА; Диапазон рабочих температур: от -60 до +125 ℃; Упаковка: Катушка и лента; Типоразмер: 2012 (0805); Технология монтажа: SMT; Изготовитель: АО "НПО "ЭРКОН"
footprint КИК-2012-Зл (Катушка индуктивности с керамическим сердечникомтипоразмер 2012(0805))
pins: 1, 2

## КИК-2012-120 нГн ±10% O
designator L?, comment 120 нГн ±10%  (value not drawn)
Катушка индуктивности с керамическим сердечником и  финишным покрытием контактных площадок оловом; Номиналиная индуктивность: 120 нГн; Добротность, не менее: 50; Резонансная частота, не менее: 1.10 ГГц; Сопротивление обмотки постоянноми току, не более: 0.51 Ом; Допустимый ток обмотки: 400 мА; Диапазон рабочих температур: от -60 до +125 ℃; Упаковка: Катушка и лента; Типоразмер: 2012 (0805); Технология монтажа: SMT; Изготовитель: АО "НПО "ЭРКОН"
footprint КИК-2012-O (Катушка индуктивности с керамическим сердечником типоразмер 2012(0805))
pins: 1, 2

## КИК-2012-120 нГн ±10% Зл
designator L?, comment 120 нГн ±10%  (value not drawn)
Катушка индуктивности с керамическим сердечником и золотым покрытием контактных площадок; Номиналиная индуктивность: 120 нГн; Добротность, не менее: 50; Резонансная частота, не менее: 1.10 ГГц; Сопротивление обмотки постоянноми току, не более: 0.51 Ом; Допустимый ток обмотки: 400 мА; Диапазон рабочих температур: от -60 до +125 ℃; Упаковка: Катушка и лента; Типоразмер: 2012 (0805); Технология монтажа: SMT; Изготовитель: АО "НПО "ЭРКОН"
footprint КИК-2012-Зл (Катушка индуктивности с керамическим сердечникомтипоразмер 2012(0805))
pins: 1, 2

## КИК-2012-150 нГн ±2% O
designator L?, comment 150 нГн ±2%  (value not drawn)
Катушка индуктивности с керамическим сердечником и  финишным покрытием контактных площадок оловом; Номиналиная индуктивность: 150 нГн; Добротность, не менее: 50; Резонансная частота, не менее: 0.92 ГГц; Сопротивление обмотки постоянноми току, не более: 0.56 Ом; Допустимый ток обмотки: 400 мА; Диапазон рабочих температур: от -60 до +125 ℃; Упаковка: Катушка и лента; Типоразмер: 2012 (0805); Технология монтажа: SMT; Изготовитель: АО "НПО "ЭРКОН"
footprint КИК-2012-O (Катушка индуктивности с керамическим сердечником типоразмер 2012(0805))
pins: 1, 2

## КИК-2012-150 нГн ±2% Зл
designator L?, comment 150 нГн ±2%  (value not drawn)
Катушка индуктивности с керамическим сердечником и золотым покрытием контактных площадок; Номиналиная индуктивность: 150 нГн; Добротность, не менее: 50; Резонансная частота, не менее: 0.92 ГГц; Сопротивление обмотки постоянноми току, не более: 0.56 Ом; Допустимый ток обмотки: 400 мА; Диапазон рабочих температур: от -60 до +125 ℃; Упаковка: Катушка и лента; Типоразмер: 2012 (0805); Технология монтажа: SMT; Изготовитель: АО "НПО "ЭРКОН"
footprint КИК-2012-Зл (Катушка индуктивности с керамическим сердечникомтипоразмер 2012(0805))
pins: 1, 2

## КИК-2012-150 нГн ±5% O
designator L?, comment 150 нГн ±5%  (value not drawn)
Катушка индуктивности с керамическим сердечником и  финишным покрытием контактных площадок оловом; Номиналиная индуктивность: 150 нГн; Добротность, не менее: 50; Резонансная частота, не менее: 0.92 ГГц; Сопротивление обмотки постоянноми току, не более: 0.56 Ом; Допустимый ток обмотки: 400 мА; Диапазон рабочих температур: от -60 до +125 ℃; Упаковка: Катушка и лента; Типоразмер: 2012 (0805); Технология монтажа: SMT; Изготовитель: АО "НПО "ЭРКОН"
footprint КИК-2012-O (Катушка индуктивности с керамическим сердечником типоразмер 2012(0805))
pins: 1, 2

## КИК-2012-150 нГн ±5% Зл
designator L?, comment 150 нГн ±5%  (value not drawn)
Катушка индуктивности с керамическим сердечником и золотым покрытием контактных площадок; Номиналиная индуктивность: 150 нГн; Добротность, не менее: 50; Резонансная частота, не менее: 0.92 ГГц; Сопротивление обмотки постоянноми току, не более: 0.56 Ом; Допустимый ток обмотки: 400 мА; Диапазон рабочих температур: от -60 до +125 ℃; Упаковка: Катушка и лента; Типоразмер: 2012 (0805); Технология монтажа: SMT; Изготовитель: АО "НПО "ЭРКОН"
footprint КИК-2012-Зл (Катушка индуктивности с керамическим сердечникомтипоразмер 2012(0805))
pins: 1, 2

## КИК-2012-150 нГн ±10% O
designator L?, comment 150 нГн ±10%  (value not drawn)
Катушка индуктивности с керамическим сердечником и  финишным покрытием контактных площадок оловом; Номиналиная индуктивность: 150 нГн; Добротность, не менее: 50; Резонансная частота, не менее: 0.92 ГГц; Сопротивление обмотки постоянноми току, не более: 0.56 Ом; Допустимый ток обмотки: 400 мА; Диапазон рабочих температур: от -60 до +125 ℃; Упаковка: Катушка и лента; Типоразмер: 2012 (0805); Технология монтажа: SMT; Изготовитель: АО "НПО "ЭРКОН"
footprint КИК-2012-O (Катушка индуктивности с керамическим сердечником типоразмер 2012(0805))
pins: 1, 2

## КИК-2012-150 нГн ±10% Зл
designator L?, comment 150 нГн ±10%  (value not drawn)
Катушка индуктивности с керамическим сердечником и золотым покрытием контактных площадок; Номиналиная индуктивность: 150 нГн; Добротность, не менее: 50; Резонансная частота, не менее: 0.92 ГГц; Сопротивление обмотки постоянноми току, не более: 0.56 Ом; Допустимый ток обмотки: 400 мА; Диапазон рабочих температур: от -60 до +125 ℃; Упаковка: Катушка и лента; Типоразмер: 2012 (0805); Технология монтажа: SMT; Изготовитель: АО "НПО "ЭРКОН"
footprint КИК-2012-Зл (Катушка индуктивности с керамическим сердечникомтипоразмер 2012(0805))
pins: 1, 2

## КИК-2012-180 нГн ±2% O
designator L?, comment 180 нГн ±2%  (value not drawn)
Катушка индуктивности с керамическим сердечником и  финишным покрытием контактных площадок оловом; Номиналиная индуктивность: 180 нГн; Добротность, не менее: 50; Резонансная частота, не менее: 0.92 ГГц; Сопротивление обмотки постоянноми току, не более: 0.64 Ом; Допустимый ток обмотки: 400 мА; Диапазон рабочих температур: от -60 до +125 ℃; Упаковка: Катушка и лента; Типоразмер: 2012 (0805); Технология монтажа: SMT; Изготовитель: АО "НПО "ЭРКОН"
footprint КИК-2012-O (Катушка индуктивности с керамическим сердечником типоразмер 2012(0805))
pins: 1, 2

## КИК-2012-180 нГн ±2% Зл
designator L?, comment 180 нГн ±2%  (value not drawn)
Катушка индуктивности с керамическим сердечником и золотым покрытием контактных площадок; Номиналиная индуктивность: 180 нГн; Добротность, не менее: 50; Резонансная частота, не менее: 0.92 ГГц; Сопротивление обмотки постоянноми току, не более: 0.64 Ом; Допустимый ток обмотки: 400 мА; Диапазон рабочих температур: от -60 до +125 ℃; Упаковка: Катушка и лента; Типоразмер: 2012 (0805); Технология монтажа: SMT; Изготовитель: АО "НПО "ЭРКОН"
footprint КИК-2012-Зл (Катушка индуктивности с керамическим сердечникомтипоразмер 2012(0805))
pins: 1, 2

## КИК-2012-180 нГн ±5% O
designator L?, comment 180 нГн ±5%  (value not drawn)
Катушка индуктивности с керамическим сердечником и  финишным покрытием контактных площадок оловом; Номиналиная индуктивность: 180 нГн; Добротность, не менее: 50; Резонансная частота, не менее: 0.92 ГГц; Сопротивление обмотки постоянноми току, не более: 0.64 Ом; Допустимый ток обмотки: 400 мА; Диапазон рабочих температур: от -60 до +125 ℃; Упаковка: Катушка и лента; Типоразмер: 2012 (0805); Технология монтажа: SMT; Изготовитель: АО "НПО "ЭРКОН"
footprint КИК-2012-O (Катушка индуктивности с керамическим сердечником типоразмер 2012(0805))
pins: 1, 2

## КИК-2012-180 нГн ±5% Зл
designator L?, comment 180 нГн ±5%  (value not drawn)
Катушка индуктивности с керамическим сердечником и золотым покрытием контактных площадок; Номиналиная индуктивность: 180 нГн; Добротность, не менее: 50; Резонансная частота, не менее: 0.92 ГГц; Сопротивление обмотки постоянноми току, не более: 0.64 Ом; Допустимый ток обмотки: 400 мА; Диапазон рабочих температур: от -60 до +125 ℃; Упаковка: Катушка и лента; Типоразмер: 2012 (0805); Технология монтажа: SMT; Изготовитель: АО "НПО "ЭРКОН"
footprint КИК-2012-Зл (Катушка индуктивности с керамическим сердечникомтипоразмер 2012(0805))
pins: 1, 2

## КИК-2012-180 нГн ±10% O
designator L?, comment 180 нГн ±10%  (value not drawn)
Катушка индуктивности с керамическим сердечником и  финишным покрытием контактных площадок оловом; Номиналиная индуктивность: 180 нГн; Добротность, не менее: 50; Резонансная частота, не менее: 0.92 ГГц; Сопротивление обмотки постоянноми току, не более: 0.64 Ом; Допустимый ток обмотки: 400 мА; Диапазон рабочих температур: от -60 до +125 ℃; Упаковка: Катушка и лента; Типоразмер: 2012 (0805); Технология монтажа: SMT; Изготовитель: АО "НПО "ЭРКОН"
footprint КИК-2012-O (Катушка индуктивности с керамическим сердечником типоразмер 2012(0805))
pins: 1, 2

## КИК-2012-180 нГн ±10% Зл
designator L?, comment 180 нГн ±10%  (value not drawn)
Катушка индуктивности с керамическим сердечником и золотым покрытием контактных площадок; Номиналиная индуктивность: 180 нГн; Добротность, не менее: 50; Резонансная частота, не менее: 0.92 ГГц; Сопротивление обмотки постоянноми току, не более: 0.64 Ом; Допустимый ток обмотки: 400 мА; Диапазон рабочих температур: от -60 до +125 ℃; Упаковка: Катушка и лента; Типоразмер: 2012 (0805); Технология монтажа: SMT; Изготовитель: АО "НПО "ЭРКОН"
footprint КИК-2012-Зл (Катушка индуктивности с керамическим сердечникомтипоразмер 2012(0805))
pins: 1, 2

## КИК-2012-220 нГн ±2% O
designator L?, comment 220 нГн ±2%  (value not drawn)
Катушка индуктивности с керамическим сердечником и  финишным покрытием контактных площадок оловом; Номиналиная индуктивность: 220 нГн; Добротность, не менее: 50; Резонансная частота, не менее: 0.82 ГГц; Сопротивление обмотки постоянноми току, не более: 0.70 Ом; Допустимый ток обмотки: 400 мА; Диапазон рабочих температур: от -60 до +125 ℃; Упаковка: Катушка и лента; Типоразмер: 2012 (0805); Технология монтажа: SMT; Изготовитель: АО "НПО "ЭРКОН"
footprint КИК-2012-O (Катушка индуктивности с керамическим сердечником типоразмер 2012(0805))
pins: 1, 2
